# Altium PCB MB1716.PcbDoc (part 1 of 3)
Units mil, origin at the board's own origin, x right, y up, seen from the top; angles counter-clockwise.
Board outline 2806.95 x 1299.21 mil, 4 copper layers (Top Layer, M1, M2, Bottom Layer), stack 62.205 mil thick; 53 components, 45 nets, 298 pads, 399 vias.
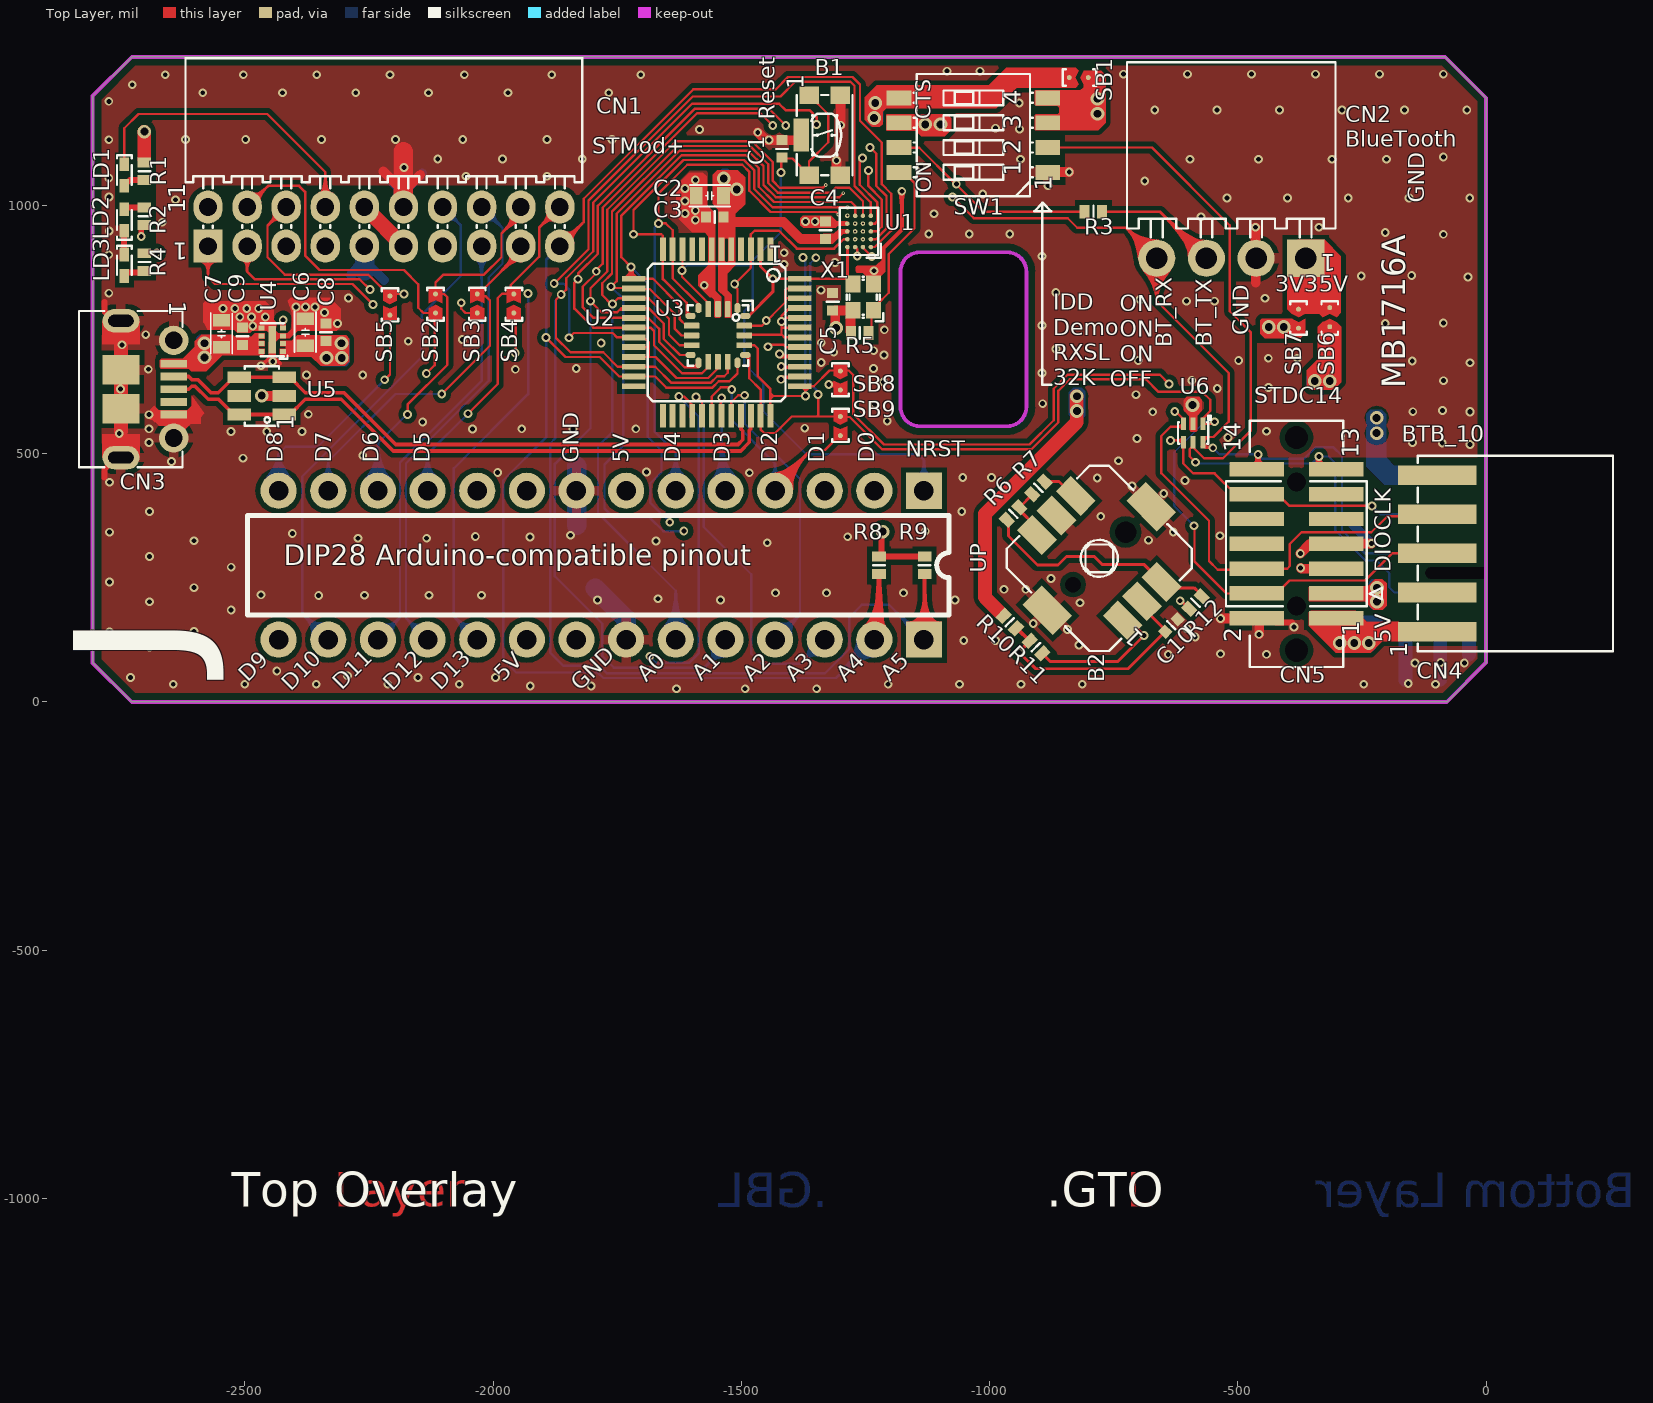
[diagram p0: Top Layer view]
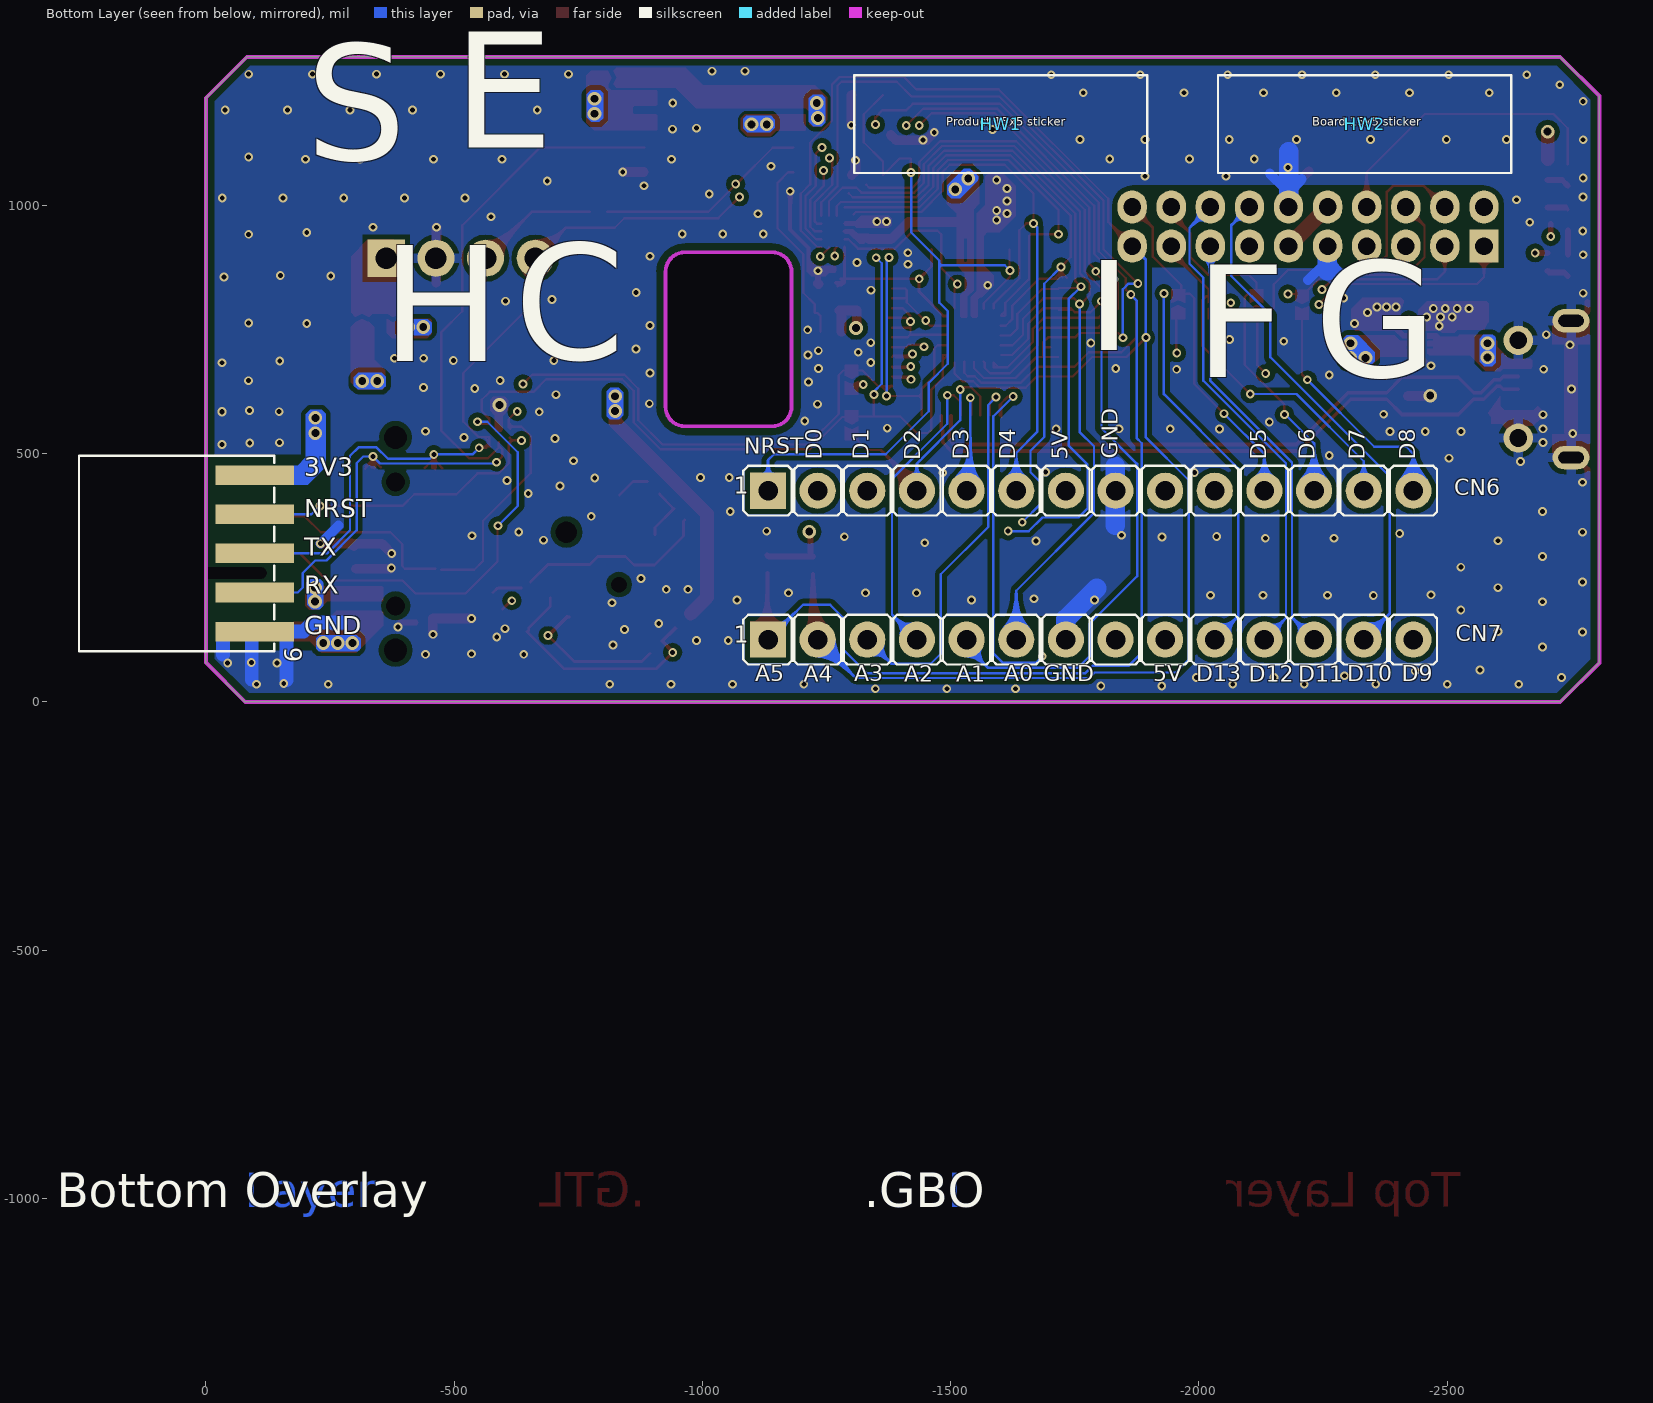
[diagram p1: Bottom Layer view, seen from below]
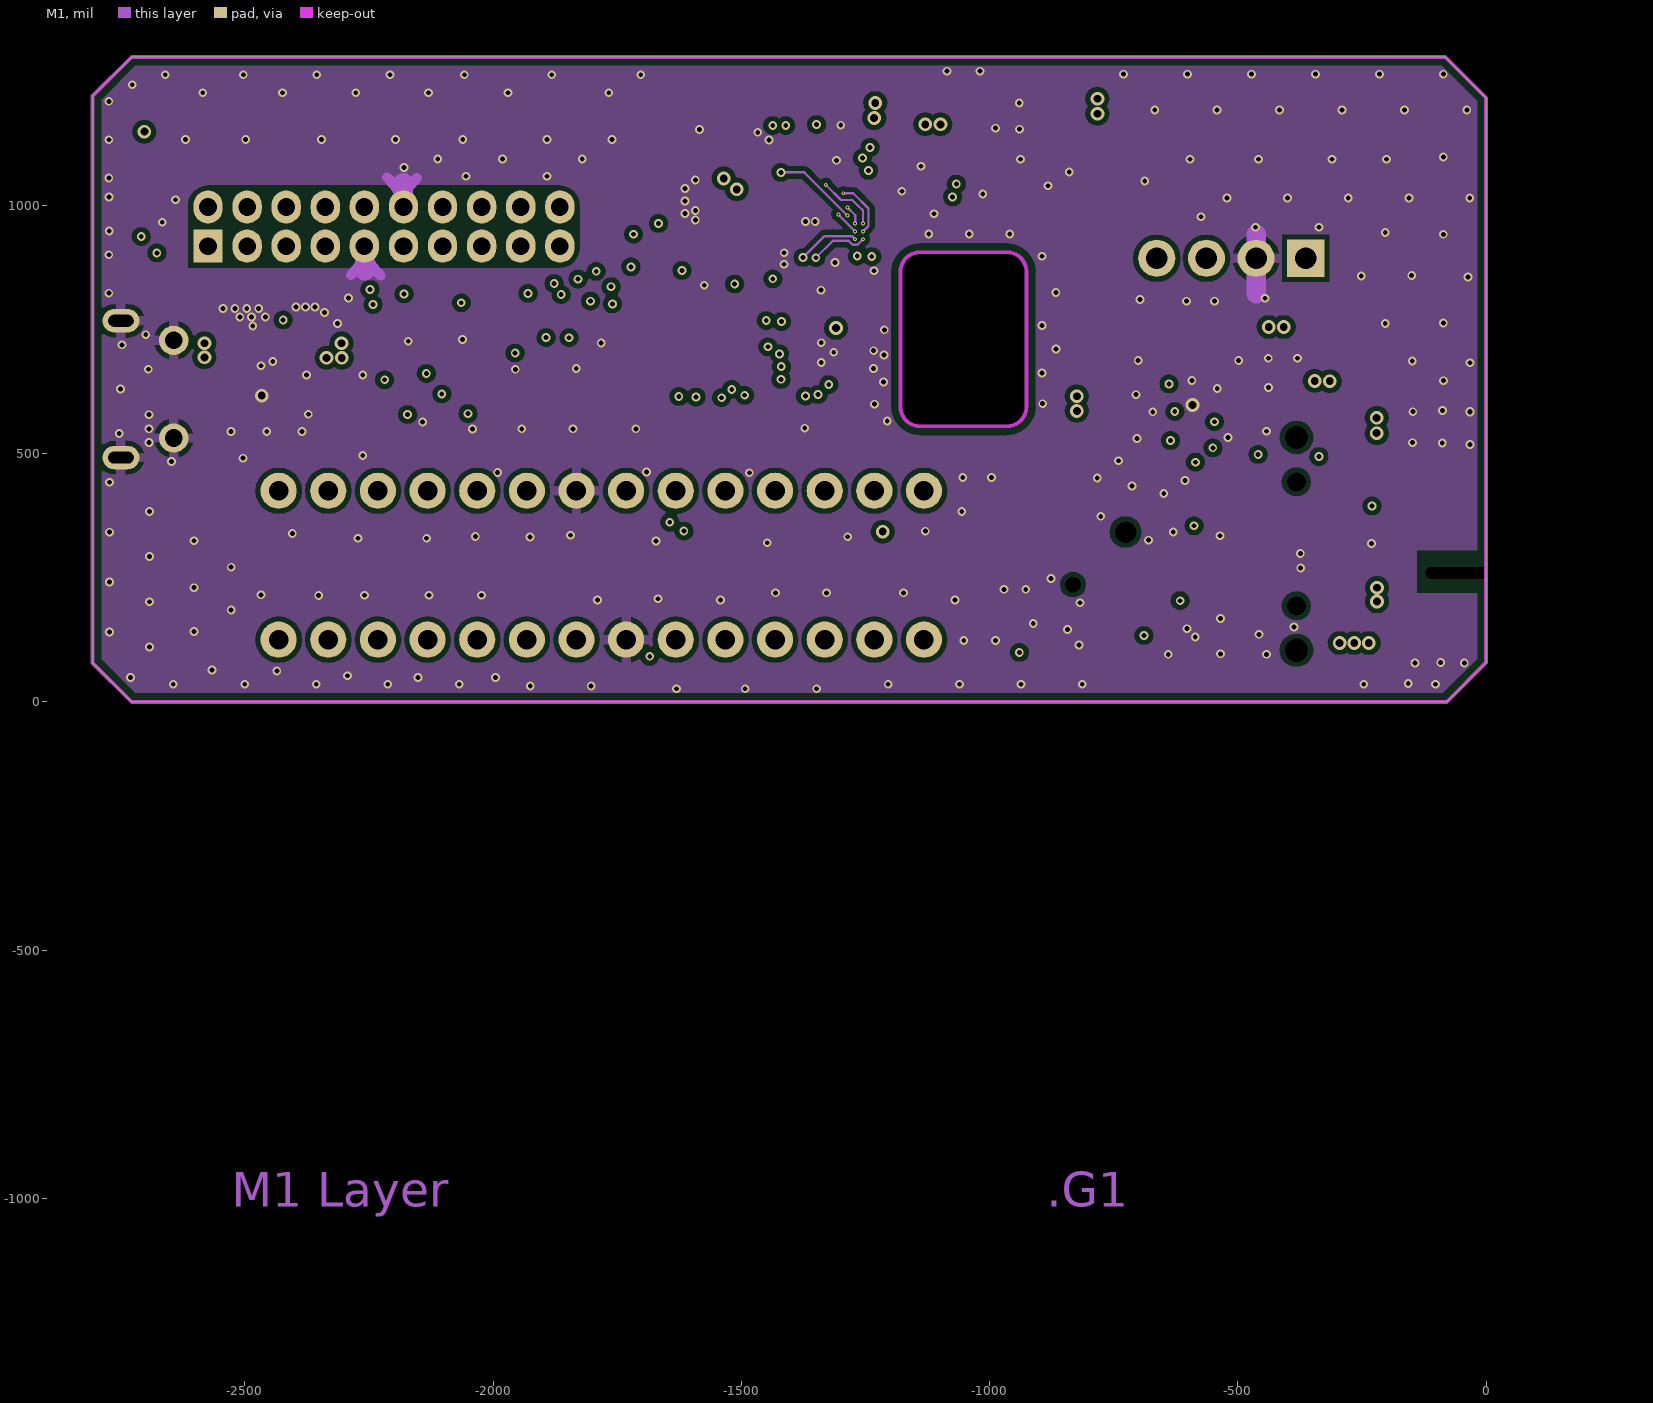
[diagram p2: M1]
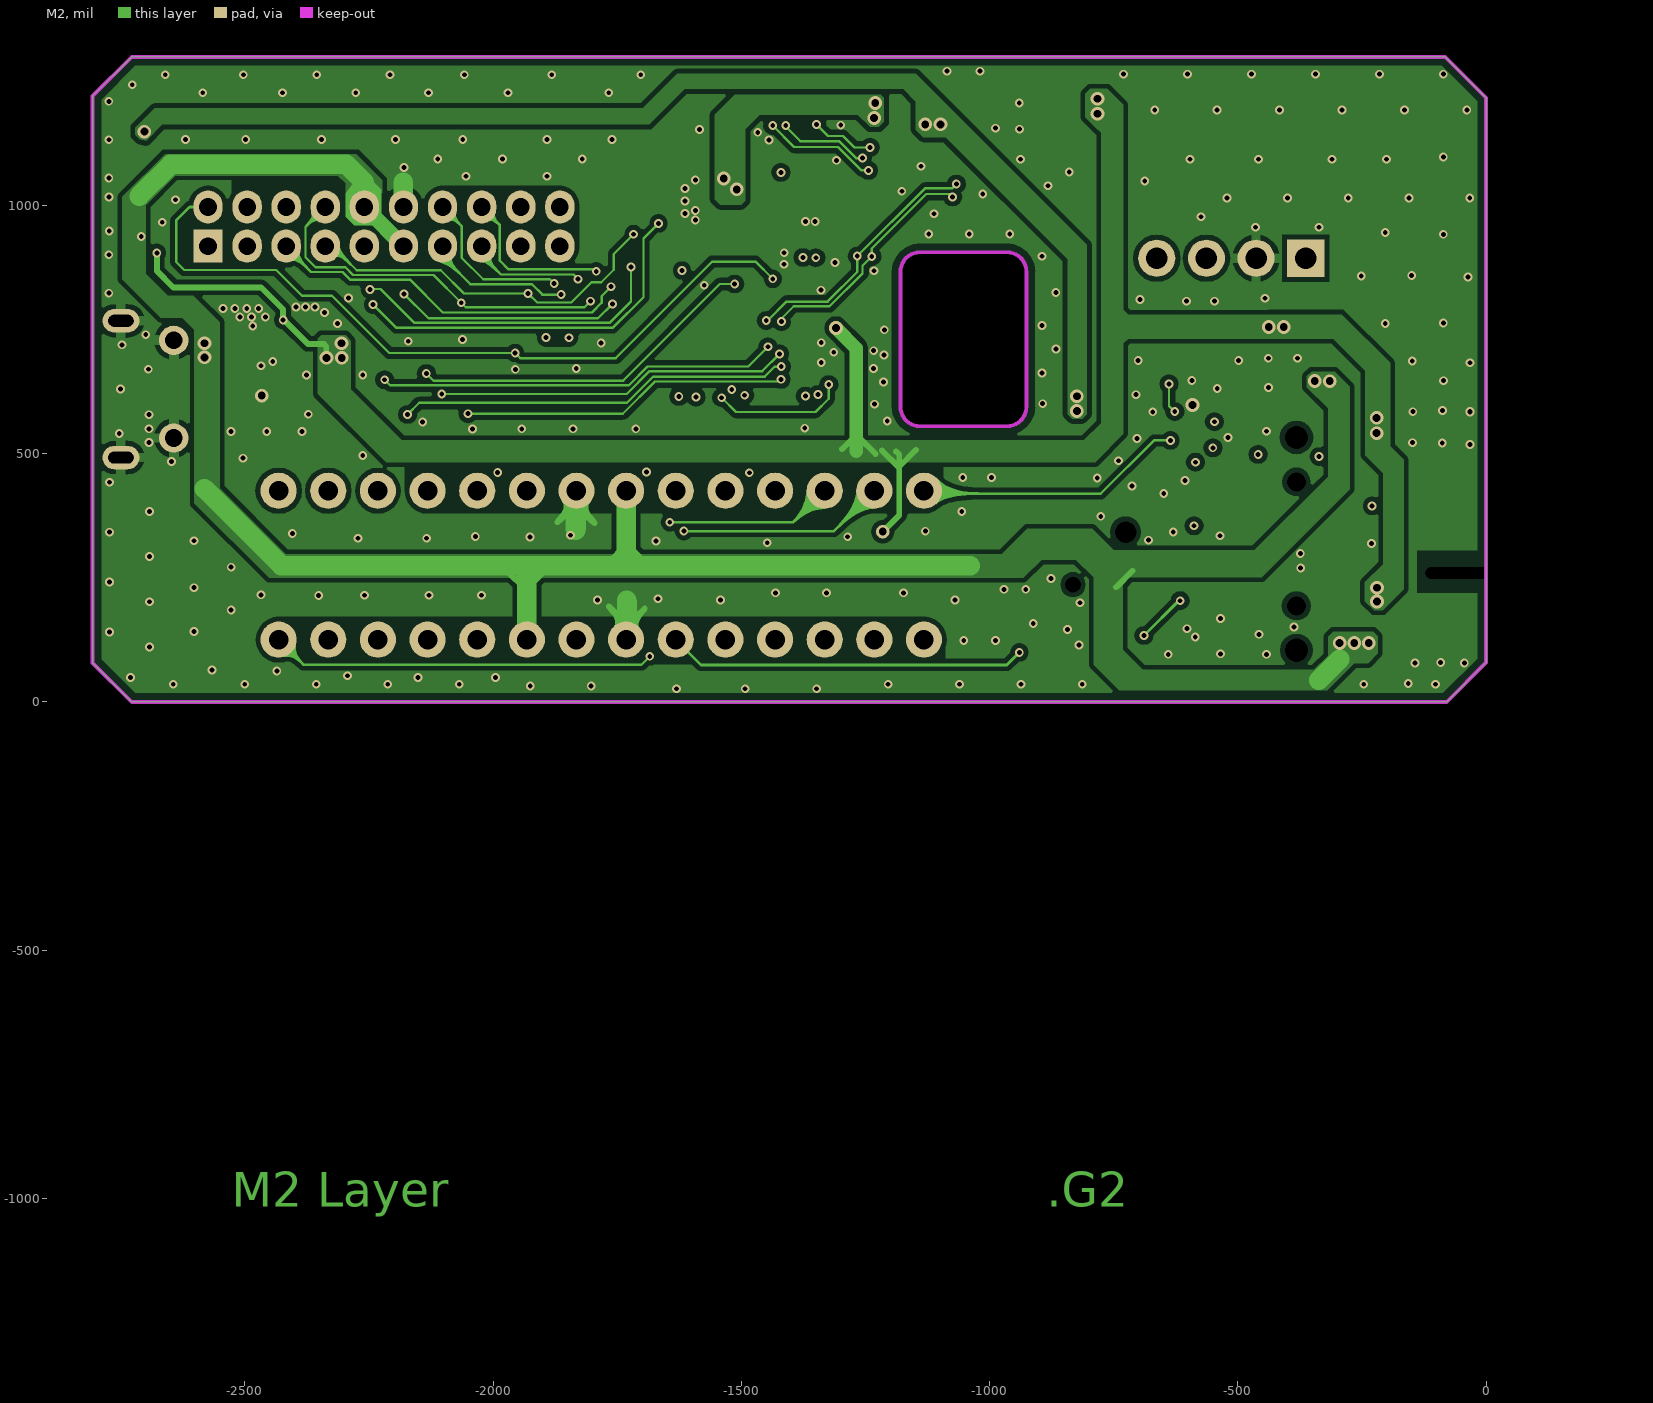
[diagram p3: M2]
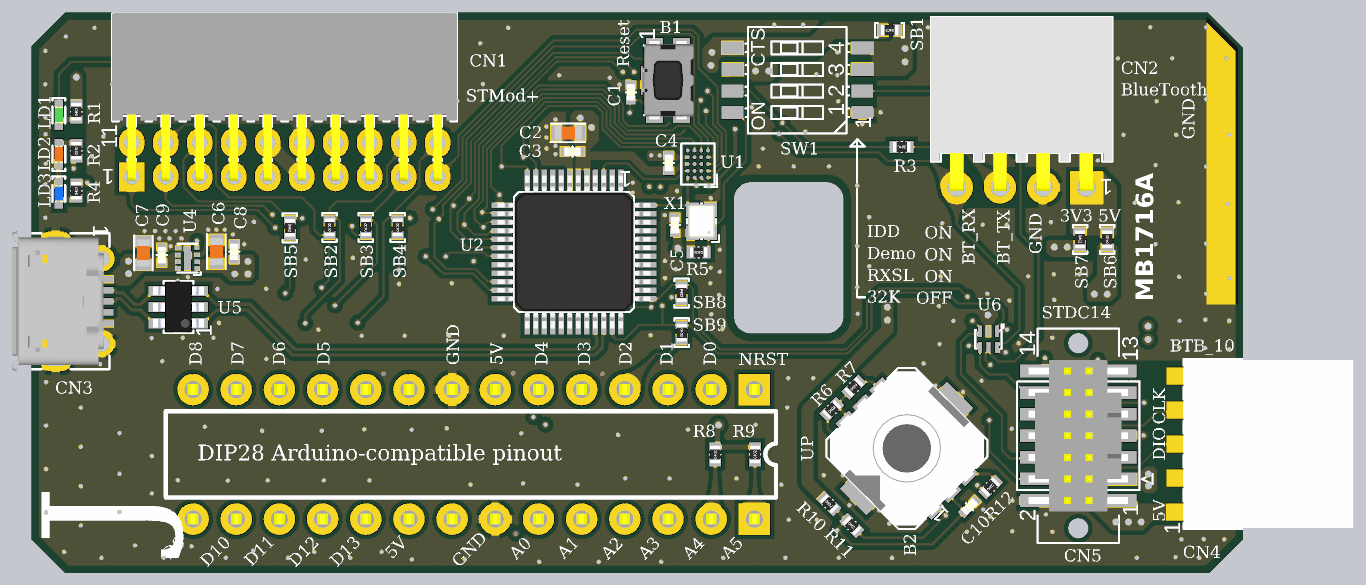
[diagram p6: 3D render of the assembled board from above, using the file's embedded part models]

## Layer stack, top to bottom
Top Solder: solder mask 0.5906, Solder Resist, Dk 3.5
Top Layer: signal copper 1.378
Dielectric 1: core 8.6614, FR-4, Dk 4.2
M1: signal copper 1.378
Dielectric 3: prepreg 39.3701, Dk 4.2
M2: signal copper 1.378
Dielectric 2: core 8.6614, Dk 4.2
Bottom Layer: signal copper 1.378
Bottom Solder: solder mask 0.5906, Solder Resist, Dk 3.5

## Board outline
-2728.21,0 -2806.95,78.74 -2806.95,1220.47 -2728.21,1299.21 -82.13,1299.21 0,1217.08 0,79.21 -79.21,0
cut-out: -1179.6,594.68 ccw(c-1140.23,594.68) -1140.23,555.32 -965.04,555.32 ccw(c-965.04,594.68) -925.67,594.68 -925.67,866.34 ccw(c-965.04,866.34) -965.04,905.71 -1140.23,905.71 ccw(c-1140.23,866.34) -1179.6,866.34

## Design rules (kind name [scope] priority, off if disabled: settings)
BoardOutlineClearance [OnLayer('Top Layer') or OnLayer('Bottom Layer') or OnLayer('Inner 1') or OnLayer('Inner 2')] p1: gap=15.75 ignorepadtopadclearanceinfootprint=FALSE except(7.87: SMDPad-OutlineEdge SMDPad-CavityEdge SMDPad-CutoutEdge SMDPad-SplitBarrior SMDPad-SplitContinuation; 10.63: Poly-OutlineEdge Poly-CavityEdge Poly-CutoutEdge Poly-SplitBarrior Poly-SplitContinuation)
Clearance Clearance_3 [ISVIA vs ISVIA] p1: gap=7.87 ignorepadtopadclearanceinfootprint=FALSE except(0: Arc-Hole Track-Hole SMDPad-Hole THPad-Hole Via-Hole Fill-Hole Poly-Hole Region-Hole Text-Hole)
Clearance Clearance_2 [INPOLYGON vs OnLayer('Keep-Out Layer')] p2: gap=13.78 ignorepadtopadclearanceinfootprint=FALSE except(0: Arc-Hole Track-Hole SMDPad-Hole THPad-Hole Via-Hole Fill-Hole Poly-Hole Region-Hole Text-Hole)
Clearance Clearance_1 [INPOLYGON] p3: gap=9.84 ignorepadtopadclearanceinfootprint=FALSE except(0: Arc-Hole Track-Hole SMDPad-Hole THPad-Hole Via-Hole Fill-Hole Poly-Hole Region-Hole Text-Hole)
Clearance [All] p4: gap=4.72 ignorepadtopadclearanceinfootprint=FALSE except(0: Arc-Hole Track-Hole SMDPad-Hole THPad-Hole Via-Hole Fill-Hole Poly-Hole Region-Hole Text-Hole)
ComponentClearance [All] p1: gap=7.87 collisioncheckmode=3 verticalgap=7.87 showdistances=FALSE
DiffPairsRouting [All] p1: maxlimit=5.91 minlimit=5.91 mostfreqgap=5.91 toplayer_minwidth=7.28 toplayer_maxwidth=7.28 toplayer_prefwidth=7.28 midlayer1_minwidth=7.28 midlayer1_maxwidth=7.28 midlayer1_prefwidth=7.28 midlayer2_minwidth=7.28 midlayer2_maxwidth=7.28 midlayer2_prefwidth=7.28 bottomlayer_minwidth=7.28 bottomlayer_maxwidth=7.28 bottomlayer_prefwidth=7.28 maxuncoupledlength=984.25
HoleSize [All] p1: absolutevalues=TRUE maxlimit=2362.2 minlimit=1 maxpercent=80.000 minpercent=20.000
HoleToHoleClearance [All] p1: gap=0 allowstackedmicrovias=TRUE
MinimumSolderMaskSliver [All] p1: minsoldermaskwidth=0
PlaneConnect [All] p1: planeconnectstyle=Relief reliefexpansion=20 reliefentries=4 reliefconductorwidth=8.27 reliefairgap=8.27
PolygonConnect PolygonConnect_3 [HasFootprint('C0402')    OR HasFootprint('C0603')  OR   HasFootprint('CRY_ECS-327MVATX-1_2X1P6_4P')] p1: connectstyle=Direct reliefconductorwidth=10 reliefentries=4 polygonreliefangle="90 Angle" airgapwidth=10
PolygonConnect PolygonConnect_1 [isvia] p2: connectstyle=Direct reliefconductorwidth=10 reliefentries=4 polygonreliefangle="90 Angle" airgapwidth=10
PolygonConnect [All] p3: connectstyle=Relief reliefconductorwidth=19.68 reliefentries=4 polygonreliefangle="90 Angle" airgapwidth=9.84
RoutingVias RoutingVias_M1 [InDrillLayerPair('Top Layer - M1')] p1: holewidth=3.94 width=7.87 viastyle="Through Hole" minholewidth=3.94 minwidth=7.87 maxholewidth=3.94 maxwidth=7.87
RoutingVias [All] p2: holewidth=11.81 width=19.68 viastyle="Through Hole" minholewidth=9.84 minwidth=17.72 maxholewidth=15.75 maxwidth=27.56
SilkToSilkClearance [All] p1: silktosilkclearance=0
SilkToSolderMaskClearance [IsPad] p1: minsilkscreentomaskgap=0 clearancetoexposedcopper=TRUE
SolderMaskExpansion SolderMaskExpansion_via [IsVia] p1: expansion=1.97 istentingtop=FALSE soldermaskfromhole=TRUE
SolderMaskExpansion [All] p2: expansion=4 istentingtop=FALSE
Width [All] p1: maxlimit=39.37 minlimit=4.72 preferedwidth=5.91
22 further rules are at their usual default settings.

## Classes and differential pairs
net class PB[12..0]: PB0 PB1 PB2 PB4 PB5 PB6 PB8 PB9 PB10 PB11 PB12
net class PA[15..0]: PA0 PA1 PA2 PA3 PA4 PA5 PA6 PA7 PA8 PA9 PA10 PA11 PA12 PA13 PA14
component class "U_STMOD Connectors": CN1
component class "Arduino Connectors": C6 C7 C8 C9 CN2 CN3 CN4 CN5 CN6 CN7 R3 R8 R9 SB2 SB3 SB4 SB5 SB6 SB7 SB8 SB9 U4 U5 U6
net class PC[15..0]: PC0 PC1 PC2 PC3 PC4 PC5 PC6 PC7 PC8 PC9 PC10 PC11 PC12 PC13 PC14 PC15
net class PD[3..0]: PD0 PD1 PD2 PD3
component class U_HW_Mechanical_Parts: HW1 HW2 HW4
component class U_STM32_microcontroller: B1 B2 C1 C2 C3 C4 C5 C10 LD1 LD2 LD3 R1 R2 R4 R5 R6 R7 R10 R11 R12 SB1 SW1 U1 U2 U3 X1
differential pair USBD: +USBD_P -USBD_N

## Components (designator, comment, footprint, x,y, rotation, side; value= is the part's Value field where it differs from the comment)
B1 "SW-PUSH-CMS_KMR2_BLACK" SWI_C&K_Y78B23110FP__ITT_KMR231GLFS -1332.24,1141.73 r90 top locked value=KMR231GLFS
B2 "Joystick MT-008A_M" SWI_XIEJIA_MT-008A_6P -779.05,289.15 r135 top locked value=MT-008A
C1 "Capacitor" C0402 -1418.23,1113.9 r270 top value=100nF (schematic designator C11)
C2 "Capacitor" C0603 -1563.62,1019.92 r0 top value=2.2uF (schematic designator C8)
C3 "Capacitor" C0402 -1553.46,976.61 r0 top value=100nF (schematic designator C7)
C4 "Capacitor" C0402 -1330.32,950.32 r270 top value=100nF (schematic designator C9)
C5 "Capacitor" C0402 -1316.06,806.22 r270 top value=100nF (schematic designator C13)
C6 "Capacitor" C0603 -2378.23,744.65 r270 top value=2.2uF (schematic designator C3)
C7 "Capacitor" C0603 -2547.28,741.65 r270 top value=10uF (schematic designator C1)
C8 "Capacitor" C0402 -2336.85,744.65 r270 top value=100nF (schematic designator C4)
C9 "Capacitor" C0402 -2504.88,736.65 r270 top value=100nF (schematic designator C2)
C10 "Capacitor" C0402 -633.81,154.06 r225 top value=10nF (schematic designator C5)
CN1 "Socket 10X2 STMod+" CON_SAMTEC_SQT-110-01-F-D-RA__STMOD+ -2220.14,957.48 r180 top locked (schematic designator CN6)
CN2 "Socket 4x1" CON_SAMTEC_SSW-104-02-G-S-RA -513.25,893.7 r180 top locked (schematic designator CN4)
CN3 "USB_uB_105017.0001" CON_USBMICROB_MOLEX_105017-0001_H2P90 -2806.95,629.92 r270 top locked value=USB_uB_105017-0001
CN4 "BTB010_061R" CON_AVX_009159010061911_BTB 0,299.13 r270 top locked value=009159010061911 (schematic designator CN7)
CN5 "Header 7x2" CON_STDC14_Receiver_MEDIUM_WITH_STDC14_3D -381.95,318.38 r90 top locked value=STDC14
CN6 "Header 14x1" CON_SAMTEC_TSW-114-07-X-S -1782.24,425.39 r180 bottom locked (schematic designator CN1)
CN7 "Header 14x1" CON_SAMTEC_TSW-114-07-X-S -1782.24,125.39 r180 bottom locked (schematic designator CN2)
HW1 "STICKER_PRODUCT" STICKER_PRODUCT_15X5 -1600.94,1163.78 r180 bottom value="Sticker product"
HW2 "STICKER_BOARD" STICKER_Board_15X5 -2333.82,1163.78 r180 bottom value="Sticker board"
LD1 "LED_green" LED_0402_KINGBRIGHT_KPHHS-1005CGCK_GREEN_1A2K_H0P5 -2743.15,1061.46 r90 top value=GREEN
LD2 "LED_red" LED_0402_KINGBRIGHT_KPHHS-1005SURCK_HYPER-RED_1A2K_H0P5 -2743.15,970.57 r270 top value=RED (schematic designator LD3)
LD3 "LED_blue" LED_0402_KINGBRIGHT_KPHHS-1005QBC-D-V_BLUE_1A2K_H0P5 -2743.15,879.69 r90 top value=BLUE (schematic designator LD2)
R1 "Resistor" R0402 -2702.75,1068.94 r90 top value=680R (schematic designator R12)
R2 "Resistor" R0402 -2702.75,978.54 r270 top value=680R (schematic designator R34)
R3 "Resistor" R0402 -790.87,987.44 r0 top value=330R
R4 "Resistor" R0402 -2702.75,886.02 r90 top value=680R (schematic designator R33)
R5 "Resistor" R0402 -1261.42,743.07 r180 top value=10K (schematic designator R4)
R6 "Resistor" R0402 -952.51,379.29 r45 top value=1K8
R7 "Resistor" R0402 -901.59,431.29 r45 top value=5K1 (schematic designator R5)
R8 "Resistor" R0402 -1222.79,275.04 r90 top value=10K (schematic designator R2)
R9 "Resistor" R0402 -1130.78,275.04 r90 top value=10K (schematic designator R1)
R10 "Resistor" R0402 -959.37,160.76 r315 top value=2K (schematic designator R9)
R11 "Resistor" R0402 -906.59,110.23 r315 top value=510R (schematic designator R8)
R12 "Resistor" R0402 -585.26,199.85 r45 top value=820R (schematic designator R7)
SB1 "SB_ON" SOLDER-BRIDGE_R0402-0R -818.86,1257.64 r180 top (schematic designator SB9)
SB2 "SB_ON" SOLDER-BRIDGE_R0402-0R -2116.22,801.1 r90 top (schematic designator SB4)
SB3 "SB_ON" SOLDER-BRIDGE_R0402-0R -2032.09,801.1 r90 top (schematic designator SB5)
SB4 "SB_ON" SOLDER-BRIDGE_R0402-0R -1958.5,801.1 r90 top (schematic designator SB3)
SB5 "SB_ON" SOLDER-BRIDGE_R0402-0R -2208.03,799.84 r270 top (schematic designator SB6)
SB6 "SB_ON" SOLDER-BRIDGE_R0402-0R -314.84,773.39 r90 top (schematic designator SB7)
SB7 "SB_ON" SOLDER-BRIDGE_R0402-0R -377.76,773.39 r270 top (schematic designator SB8)
SB8 "SB_ON" SOLDER-BRIDGE_R0402-0R -1300.63,648.86 r270 top (schematic designator SB2)
SB9 "SB_ON" SOLDER-BRIDGE_R0402-0R -1300.55,557.13 r270 top (schematic designator SB1)
SW1 "SWITCH_4WAY" SWI_CTS_CTS218-4LP -1032.75,1141.73 r90 top locked value=CT218-4LPSTRI
U1 "STM32G051F8Y6" ICC_WLCSP20_1P94X2P40_P040 -1262.97,947.74 r180 top locked (schematic designator U4)
U2 "STM32C031C6T6" ICC_LQFP48_7X7_P050 -1549.92,744.09 r180 top locked (schematic designator U3)
U3 "STM32C011F6U6" ICC_UFQFPN20_3X3_P050 -1547.24,738.19 r270 top locked (schematic designator U2)
U4 "LD56100" ESD_DFN8-EPAD_1P6X1P2_P040_H0P45 -2445,729.61 r90 top locked value=LD56100DPU33R (schematic designator U1)
U5 "USBLC6-2SC6" ESD_SOT23-6L -2466.06,616.34 r90 top (schematic designator U6)
U6 "ESDALC6V1-5M6" ESD_UQFN-6L_1P45X1_P050 -590.11,541.77 r180 top locked (schematic designator U5)
X1 "ECS-327MVATX" CRY_ECS-327MVATX-1_2X1P6_4P -1254.61,815.16 r90 top value=ECS-327MVATX-1-CN-TR

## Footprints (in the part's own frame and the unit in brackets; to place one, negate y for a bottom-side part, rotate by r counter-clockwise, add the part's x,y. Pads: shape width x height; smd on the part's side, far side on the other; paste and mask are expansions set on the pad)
C0402 [mm]
  rect 0.51x0.56 smd mask+0.05: 1(-0.45,0) 2(0.45,0)
  silkscreen extent 0,-0.3 0,0.3, body extent -0.5,-0.3 0.5,0.3, height 0.4
C0603 [mm]
  rect 0.64x0.89 smd mask+0.05: 1(-0.7,0) 2(0.7,0)
  silkscreen extent -1.05,-0.55 1.02,0.55, body extent -0.9,-0.5 0.9,0.5, height 1.4
CON_AVX_009159010061911_BTB [mm] "MCD-02332"
  round 0 hole 3.4 slot 0.6 at 0 deg unplated mask+0.05: 0(1,-1.4)
  rect 1x4 smd paste-2 mask+0.05: 1(4,-2.5) 2(2,-2.5) 3(0,-2.5) 4(-2,-2.5) 5(-4,-2.5)
  rect 1x4 smd far side paste-2 mask+0.05: 6(4,-2.5) 7(2,-2.5) 8(0,-2.5) 9(-2,-2.5) 10(-4,-2.5)
  silkscreen extent -5,-3.5 5,6.5, body extent -4.95,-3.5 4.95,6.5, height 1.7
CON_SAMTEC_SQT-110-01-F-D-RA__STMOD+ [mm] "SQT-110-01-F-D-RA (connecteur SAMTEC pour interface STMod+ femelle cot?Host) Pinning adapt?non conforme SAMTEC."
  rect 1.5x1.7 hole 0.9 mask+0.05: 1(9,1)
  oval 1.5x1.7 hole 0.9 mask+0.05: 2(7,1) 3(5,1) 4(3,1) 5(1,1) 6(-1,1) 7(-3,1) 8(-5,1) 9(-7,1) 10(-9,1) 11(9,-1) 12(7,-1) 13(5,-1) 14(3,-1) 15(1,-1) 16(-1,-1) 17(-3,-1) 18(-5,-1) 19(-7,-1) 20(-9,-1)
  silkscreen extent -10.15,-8.62 10.15,0.07, body extent -10.15,-8.65 10.15,1.22, height 4
CON_SAMTEC_SSW-104-02-G-S-RA [mm] "MCD-02305"
  rect 1.9x1.9 hole 1.1 mask+0.05: 1(-3.81,0)
  round 1.9 hole 1.1 mask+0.05: 2(-1.27,0) 3(1.27,0) 4(3.81,0)
  silkscreen extent -5.34,-10.03 5.34,-1.07, body extent -5.33,-10.03 5.33,0.2, height 2.41
CON_SAMTEC_TSW-114-07-X-S [mm] "MCD-02306"
  rect 1.85x1.85 / inner round 1.85 / far side rect 1.85x1.85 hole 1 mask+0.05: 1(-16.51,0)
  round 1.85 hole 1 mask+0.05: 2(-13.97,0) 3(-11.43,0) 4(-8.89,0) 5(-6.35,0) 6(-3.81,0) 7(-1.27,0) 8(1.27,0) 9(3.81,0) 10(6.35,0) 11(8.89,0) 12(11.43,0) 13(13.97,0) 14(16.51,0)
  silkscreen extent -17.78,-1.27 17.72,1.27, body extent -17.91,-1.27 17.78,1.27, height 8.38
CON_STDC14_Receiver_MEDIUM_WITH_STDC14_3D [mm] "compatible with FTSH-107-01-L-DV,-K,-A,-P,-ES"
  round 0 hole 1.19 unplated mask+0.05: 0(-5.445,0) 0(5.445,0)
  round 0 hole 0.97 unplated mask+0.05: 0(-3.175,0) 0(3.175,0)
  rect 0.74x2.79 smd mask+0.05: 1(-3.81,-2.032) 2(-3.81,2.032) 3(-2.54,-2.032) 4(-2.54,2.032) 5(-1.27,-2.032) 6(-1.27,2.032) 7(0,-2.032) 8(0,2.032) 9(1.27,-2.032) 10(1.27,2.032) 11(2.54,-2.032) 12(2.54,2.032) 13(3.81,-2.032) 14(3.81,2.032)
  silkscreen extent -6.3,-4.38 6.3,3.6, body extent -6.3,-2.92 6.3,2.92, height 6.6
CON_USBMICROB_MOLEX_105017-0001_H2P90 [mm]
  rect 0.4x1.35 smd mask+0.05: 1(-1.3,4.15) 2(-0.65,4.15) 3(0,4.15) 4(0.65,4.15) 5(1.3,4.15)
  round 1.5 hole 0.9 mask+0.05: 6(-2.5,4.15) 7(2.5,4.15)
  oval 1.2x1.9 hole 0.6 slot 1.3 at 90 deg mask+0.05: 8(3.5,1.45) 9(-3.5,1.45)
  rect 1.5x1.9 smd mask+0.05: 10(-1,1.45) 11(1,1.45)
  Top Layer region: 2.3,2.4 3.5,2.4 3.5,0.5 2.3,0.5 2.3,2.4
  Top Layer region: -3.5,2.4 -2.3,2.4 -2.3,0.5 -3.5,0.5 -3.5,2.4
  silkscreen extent -4,-0.7 4,4.6, body extent -4.1,-1.15 4.1,4.66, height 2.9
CRY_ECS-327MVATX-1_2X1P6_4P [mm] "MCD-02331"
  rect 0.85x0.75 smd mask+0.05: 1(-0.675,-0.525) 2(0.675,-0.525) 3(0.675,0.525) 4(-0.675,0.525)
  silkscreen extent -1.23,-1.02 1.05,0.85, body extent -1.05,-0.85 1.05,0.85, height 0.91
ESD_DFN8-EPAD_1P6X1P2_P040_H0P45 [mm] "MCD-02304"
  rect 0.26x0.3 smd mask+0.035: 1(-0.6,-0.55) 2(-0.2,-0.55) 3(0.2,-0.55) 4(0.6,-0.55) 5(0.6,0.55) 6(0.2,0.55) 7(-0.2,0.55) 8(-0.6,0.55)
  rect 1.4x0.4 smd mask+0.05: 9(0,0)
  silkscreen extent -0.97,-0.77 0.85,0.6, body extent -0.8,-0.65 0.8,0.65, height 0.51
ESD_SOT23-6L [mm]
  rect 0.6x1.2 smd mask+0.05: 1(-0.95,-1.15) 2(0,-1.15) 3(0.95,-1.15) 4(0.95,1.15) 5(0,1.15) 6(-0.95,1.15)
  silkscreen extent -1.53,-0.87 1.53,0.87, body extent -1.52,-1.5 1.52,1.5, height 1.45
ESD_UQFN-6L_1P45X1_P050 [mm]
  rect 0.25x0.65 smd mask+0.05: 1(-0.5,-0.475) 2(0,-0.475) 3(0.5,-0.475) 4(0.5,0.475) 5(0,0.475) 6(-0.5,0.475)
  silkscreen extent -0.9,-0.87 0.77,0.55, body extent -0.77,-0.55 0.77,0.55, height 0.66
ICC_LQFP48_7X7_P050 [mm]
  rect 0.3x1.2 smd mask+0.05: 1(-2.75,-4.25) 2(-2.25,-4.25) 3(-1.75,-4.25) 4(-1.25,-4.25) 5(-0.75,-4.25) 6(-0.25,-4.25) 7(0.25,-4.25) 8(0.75,-4.25) 9(1.25,-4.25) 10(1.75,-4.25) 11(2.25,-4.25) 12(2.75,-4.25) 25(2.75,4.25) 26(2.25,4.25) 27(1.75,4.25) 28(1.25,4.25) 29(0.75,4.25) 30(0.25,4.25) 31(-0.25,4.25) 32(-0.75,4.25) 33(-1.25,4.25) 34(-1.75,4.25) 35(-2.25,4.25) 36(-2.75,4.25)
  rect 1.2x0.3 smd mask+0.05: 13(4.25,-2.75) 14(4.25,-2.25) 15(4.25,-1.75) 16(4.25,-1.25) 17(4.25,-0.75) 18(4.25,-0.25) 19(4.25,0.25) 20(4.25,0.75) 21(4.25,1.25) 22(4.25,1.75) 23(4.25,2.25) 24(4.25,2.75) 37(-4.25,2.75) 38(-4.25,2.25) 39(-4.25,1.75) 40(-4.25,1.25) 41(-4.25,0.75) 42(-4.25,0.25) 43(-4.25,-0.25) 44(-4.25,-0.75) 45(-4.25,-1.25) 46(-4.25,-1.75) 47(-4.25,-2.25) 48(-4.25,-2.75)
  silkscreen extent -3.52,-3.52 3.52,3.52, body extent -4.5,-4.5 4.5,4.5, height 1.6
ICC_UFQFPN20_3X3_P050 [mm] "MCD-02302"
  oct 0.525x0.3 smd mask+0.05: 1(-1.4,1) 5(-1.4,-1) 11(1.4,-1) 15(1.4,1)
  rrect25% 0.8x0.3 smd mask+0.05: 2(-1.35,0.5) 3(-1.35,0) 4(-1.35,-0.5) 12(1.35,-0.5) 13(1.35,0) 14(1.35,0.5)
  oct 0.3x0.525 smd mask+0.05: 6(-1,-1.4) 10(1,-1.4) 16(1,1.4) 20(-1,1.4)
  rrect25% 0.3x0.8 smd mask+0.05: 7(-0.5,-1.35) 8(0,-1.35) 9(0.5,-1.35) 17(0.5,1.35) 18(0,1.35) 19(-0.5,1.35)
  silkscreen extent -1.78,-1.55 1.54,1.78, body extent -1.5,-1.5 1.5,1.5, height 0.55
ICC_WLCSP20_1P94X2P40_P040 [mm] "MCD-02303"
  round 0.23 smd mask+0.05: A1(-0.6,0.8) A2(-0.2,0.8) A3(0.2,0.8) A4(0.6,0.8) B1(-0.6,0.4) B2(-0.2,0.4) B3(0.2,0.4) B4(0.6,0.4) C1(-0.6,0) C2(-0.2,0) C3(0.2,0) C4(0.6,0) D1(-0.6,-0.4) D2(-0.2,-0.4) D3(0.2,-0.4) D4(0.6,-0.4) E1(-0.6,-0.8) E2(-0.2,-0.8) E3(0.2,-0.8) E4(0.6,-0.8)
  silkscreen extent -1.12,-1.21 0.98,1.35, body extent -0.98,-1.21 0.98,1.21, height 0.6
LED_0402_KINGBRIGHT_KPHHS-1005CGCK_GREEN_1A2K_H0P5 [mm] "MCD-00707"
  rect 0.7x0.5 smd mask+0.05: 1(-0.55,0) 2(0.55,0)
  silkscreen extent -0.5,-0.38 1,0.38, body extent -0.5,-0.3 0.51,0.3, height 0.6
LED_0402_KINGBRIGHT_KPHHS-1005QBC-D-V_BLUE_1A2K_H0P5 [mm] "MCD-00706"
  rect 0.7x0.5 smd mask+0.05: 1(-0.55,0) 2(0.55,0)
  silkscreen extent -0.5,-0.38 1,0.38, body extent -0.5,-0.3 0.51,0.3, height 0.6
LED_0402_KINGBRIGHT_KPHHS-1005SURCK_HYPER-RED_1A2K_H0P5 [mm] "MCD-00708"
  rect 0.7x0.5 smd mask+0.05: 1(-0.55,0) 2(0.55,0)
  silkscreen extent -0.5,-0.38 1,0.38, body extent -0.5,-0.3 0.51,0.3, height 0.6
R0402 [mm]
  rect 0.51x0.7 smd mask+0.05: 1(-0.45,0) 2(0.45,0)
  silkscreen extent 0,-0.3 0,0.3, body extent -0.52,-0.3 0.52,0.3, height 0.4
SOLDER-BRIDGE_R0402-0R [mil] "MCD-01619"
  round 10 smd paste-393.7: 1(-17.72,0) 2(20.67,0)
  Top Layer region: -30.51,-13.78 -30.51,13.78 -8.37,13.78 -1.48,0 -8.37,-13.78
  Top Layer region: 1.48,13.78 8.37,0 1.48,-13.78 30.51,-13.78 30.51,13.78
  silkscreen extent -33,-17 33,17, body extent -20,-12 20,12, height 14
STICKER_Board_15X5 [mil] "Sticker to mention board CPN code"
  silkscreen extent -295,-98 295,98, body extent -295,-98 295,98, height 0
STICKER_PRODUCT_15X5 [mil] "Sticker to mention board CPN code"
  silkscreen extent -295,-98 295,98, body extent -295,-98 295,98, height 0
SWI_C&K_Y78B23110FP__ITT_KMR231GLFS [mm] "MCD-00715"
  rect 0.9x1 smd mask+0.05: 1(2.05,0.8) 2(2.05,-0.8) 3(-2.05,0.8) 4(-2.05,-0.8)
  rect 1.7x0.8 smd mask+0.05: 5(0,1.2)
  silkscreen extent -2.05,-1.43 2.05,1.43, body extent -2.3,-1.5 2.3,1.5, height 2.1
SWI_CTS_CTS218-4LP [mm] "GULL WING TERMINAL"
  rect 0.76x1.27 smd mask+0.05: 1(-1.905,-3.81) 2(-0.635,-3.81) 3(0.635,-3.81) 4(1.905,-3.81) 5(1.905,3.81) 6(0.635,3.81) 7(-0.635,3.81) 8(-1.905,3.81)
  silkscreen extent -3.13,-3.05 3.13,3.05, body extent -3.18,-4.32 3.18,4.32, height 2.85
SWI_XIEJIA_MT-008A_6P [mm] "MCD-00132"
  rect 1.8x1.1 smd mask+0.05: 1(-3.1,1.4) 2(-3.1,0) 3(-3.1,-1.4) 4(3.1,1.4) 5(3.1,0) 6(3.1,-1.4)
  rect 2.2x1.4 smd mask+0.05: 7(0,3.75) 8(0,-3.75)
  round 0 hole 0.8 unplated paste-10 mask+0.05: NPTH1(0,1.9)
  round 0 hole 1.1 unplated paste-10 mask+0.05: NPTH2(0,-1.9)
  silkscreen extent -3.7,-3.7 3.7,3.7, body extent -3.85,-3.75 3.85,3.75, height 5.2

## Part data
B1: library part MCD-01485, "Microminiature Tact Switch for SMT - KMR 2 Series - 1.9 mm height", Manufacturer=C&K, Manufacturer_Part_Number=KMR231GLFS
B2: library part MCD-00132, "Joystick, 4 dir, 1 OK", Manufacturer="XIEJIA ELECTRONICS", Manufacturer_Part_Number=MT-008A
C1 C3 C4 C5 C8 C9: library part MCD-00006, "Capacitor, MLCC, 100nF, 16V, X7R, +/-10%, 0402, T=0.5mm", Alternate_Manufacturer=MURATA, Alternate_Manufacturer_Part_Number=GCM155R71C104KA55D, Manufacturer=YAGEO, Manufacturer_Part_Number=CC0402KRX7R7BB104, Package=C0402
C2 C6: library part MCD-00654, "Capacitor, MLCC, 2.2uF, 16V, X5R,+/-10%, 0603, T=0.8mm", Alternate_Manufacturer=MURATA, Alternate_Manufacturer_Part_Number=GCM155R71C104KA55D, Manufacturer=YAGEO, Manufacturer_Part_Number=CC0603KRX5R7BB225, Package=C0603
C7: library part MCD-01124, "Capacitor, MLCC, 10uF, 10V, X5R, +/-10%, 0603, T=0.8mm", Alternate_Manufacturer=MURATA, Alternate_Manufacturer_Part_Number=GCM155R71C104KA55D, Manufacturer_Part_Number=GRM188R61A106KAAL, Package=C0603
C10: library part MCD-00011, "Capacitor, MLCC, 10nF, 16V, X7R, +/-10%, 0402, T=0.5mm", Alternate_Manufacturer=MURATA, Alternate_Manufacturer_Part_Number=GCM155R71C104KA55D, Manufacturer=YAGEO, Manufacturer_Part_Number=CC0402KRX7R7BB103, Package=C0402
CN1: library part MCD-00309, "Socket 10x2, 2.00mm, RA, TH, Height 6.35mm/2.29mm", Alternate_Manufacturer=JIUBABA;CONNECT, Alternate_Manufacturer_Part_Number=FH200020C-12300;CNT-F200-2*10-GD-635/2.3, Manufacturer=SAMTEC, Manufacturer_Part_Number=SQT-110-01-F-D-RA
CN2: library part MCD-02305, "Socket, 4x1, 2.54mm, RA, TH, height 10.67/2.41mm", Alternate_Manufacturer=N/A, Manufacturer=SAMTEC, Manufacturer_Part_Number=SSW-104-02-G-S-RA
CN3: library part MCD-00028, "USB-MICRO-B, 0.65mm, RA, SMT, Bottom Mount,", Manufacturer=MOLEX, Manufacturer_Part_Number=1050170001
CN4: library part MCD-02332, "SSL Connector, 10 Position Adapter, Bridge Board to Board - Card Edge 0.079\" (2.00mm)", Alternate_Manufacturer=N/A, Manufacturer=AVX, Manufacturer_Part_Number=009159010061911
CN5: library part MCD-01241, "Header 7x2, 1.27mm, Dual row, Straight, \"STDC14_MEDIUM\" : footprint compatible with FTSH-107-01-L-DV,-K,-A,-P,-ES (use \"STDC14_BIG\" to also be compatible with SHF-107-01-L-D-SM,-K) and FTSH-105-01-L-DV-K (MIPI10)", Manufacturer=SAMTEC, Manufacturer_Part_Number=FTSH-107-01-L-DV-K
CN6 CN7: library part MCD-02306, "Header, 14x1, 2,54mm, VR, TH, Height 5.84mm/2.54mm", Alternate_Manufacturer=N/A, Manufacturer=SAMTEC, Manufacturer_Part_Number=TSW-114-07-G-S
HW1: library part MCD-02191, "Sticker product 15x5 mm", Alternate_Manufacturer=N/A
HW2: library part MCD-02192, "Sticker board 15x5 mm", Alternate_Manufacturer=N/A
LD1: library part MCD-00707, "LED 0402 Green", Alternate_Manufacturer="OSRAM OPTO SEMICONDUCTORS", Alternate_Manufacturer_Part_Number="LG Q396-PS-35", Manufacturer=KINGBRIGHT, Manufacturer_Part_Number=KPHHS-1005CGCK, Package="LED 0402"
LD2: library part MCD-00708, "LED 0402 Red", Alternate_Manufacturer="OSRAM OPTO SEMICONDUCTORS", Alternate_Manufacturer_Part_Number="LS Q976-NR-1", Manufacturer=KINGBRIGHT, Manufacturer_Part_Number=KPHHS-1005SURCK, Package="LED 0402"
LD3: library part MCD-00706, "LED 0402 Blue", Manufacturer=KINGBRIGHT, Manufacturer_Part_Number=KPHHS-1005QBC-D-V, Package="LED 0402"
R1 R2 R4: library part MCD-00507, "Resistor,680R,0402,1%,1/16W", Alternate_Manufacturer=YAGEO, Alternate_Manufacturer_Part_Number=RT0402FRE07100KL, Manufacturer_Part_Number=RC0402FR-07680RL, Package=R0402
R3: library part MCD-00062, "Resistor,330R,0402,1%,1/16W", Alternate_Manufacturer=YAGEO, Alternate_Manufacturer_Part_Number=RT0402FRE07100KL, Manufacturer_Part_Number=RC0402FR-07330RL, Package=R0402
R5 R8 R9: library part MCD-00053, "Resistor,10K,0402,1%,1/16W", Alternate_Manufacturer=YAGEO, Alternate_Manufacturer_Part_Number=RT0402FRE07100KL, Manufacturer_Part_Number=RC0402FR-0710KL, Package=R0402
R6: library part MCD-00409, "Resistor,1K8,0402,1%,1/16W", Alternate_Manufacturer=YAGEO, Alternate_Manufacturer_Part_Number=RT0402FRE07100KL, Manufacturer_Part_Number=RC0402FR-071K8L, Package=R0402
R7: library part MCD-00333, "Resistor,5K1,0402,1%,1/16W", Alternate_Manufacturer=YAGEO, Alternate_Manufacturer_Part_Number=RT0402FRE07100KL, Manufacturer_Part_Number=RC0402FR-075K1L, Package=R0402
R10: library part MCD-00419, "Resistor,2K,0402,1%,1/16W", Alternate_Manufacturer=YAGEO, Alternate_Manufacturer_Part_Number=RT0402FRE07100KL, Manufacturer_Part_Number=RC0402FR-072KL, Package=R0402
R11: library part MCD-00064, "Resistor,510R,0402,1%,1/16W", Alternate_Manufacturer=YAGEO, Alternate_Manufacturer_Part_Number=RT0402FRE07100KL, Manufacturer_Part_Number=RC0402FR-07510RL, Package=R0402
R12: library part MCD-00527, "Resistor,820R,0402,1%,1/16W", Alternate_Manufacturer=YAGEO, Alternate_Manufacturer_Part_Number=RT0402FRE07100KL, Manufacturer_Part_Number=RC0402FR-07820RL, Package=R0402
SB1 SB2 SB3 SB4 SB5 SB6 SB7 SB8 SB9: library part MCD-01618, "Solder Bridge 0402 ON", Manufacturer=YAGEO, Manufacturer_Part_Number=RC0402JR-070RL, Package=SB0402
SW1: library part MCD-00167, "Quad SPST surface mount switch. 1.27mm pitch. Tinned legs.", Manufacturer=CTS, Manufacturer_Part_Number=CT218-4LPSTRI
U1: library part MCD-02303, "MCU, ARM™-based 32-bit MCU Cortex-M0+", Alternate_Manufacturer=N/A, Manufacturer=STMICROELECTRONICS, Package=WLCSP20
U2: library part MCD-02301, "MCU, ARM™-based 32-bit MCU Cortex-M0+, 32KB Flash, 6KB SRAM", Alternate_Manufacturer=N/A, Manufacturer=STMICROELECTRONICS, Package=LQFP48
U3: library part MCD-02313, "MCU, ARM™-based 32-bit MCU Cortex-M0+, 32KB Flash, 6KB SRAM", Alternate_Manufacturer=N/A, Manufacturer=STMICROELECTRONICS, Package=UFQFPN20
U4: library part MCD-02304, "LDO, 1 A very low dropout fast transient ultra-low noise linear regulator", Alternate_Manufacturer=N/A, Manufacturer=STMICROELECTRONICS, Manufacturer_Part_Number=LD56100DPU33R, Package=DFN8
U5: library part MCD-00163, "Very low capacitance ESD protection", Manufacturer=STMICROELECTRONICS, Manufacturer_HQ_COO=EU
U6: library part MCD-01457, "ESD protection , 5 lines", Manufacturer=STMICROELECTRONICS, Manufacturer_HQ_COO=EU, Package=QFN
X1: library part MCD-02331, "Oscillator 32.768KHz, +-25ppm, Vcc: 1.6V ~ 3.3V , Tri-State pin, SMD", Alternate_Manufacturer=N/A, Manufacturer="ECS INC. INTERNATIONAL", Manufacturer_Part_Number=ECS-327MVATX-1-CN-TR, Package=2.0x1.6mm

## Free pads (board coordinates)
  round 20 on Mech16: 1(-2067.11,-1289.78) 1(-143.98,-1289.78)

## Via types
v1: diameter 17.72, hole 9.84, Top Layer to Bottom Layer, tented both sides, 357 vias
v2: diameter 27.56, hole 15.75, Top Layer to Bottom Layer, tented both sides, 31 vias
v3: diameter 7.87, hole 3.94, Top Layer to M1, tented both sides, 11 vias

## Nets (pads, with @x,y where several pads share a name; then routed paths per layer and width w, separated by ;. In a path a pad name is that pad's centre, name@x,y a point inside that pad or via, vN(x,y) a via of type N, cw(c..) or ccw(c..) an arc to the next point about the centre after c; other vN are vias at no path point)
3V3: C5.2 C6.2 C8.2 CN4.10 CN5.3 R4.2 R5.2 R8.2 R9.2 SB1.1 SB7.2 SW1.3 SW1.4 U4.1 U4.2 U4.4 X1.4 | length 1635.5
  Top Layer w11.81: R4.2@-2702.75,903.74 -2702.16,904.33 v1@-2675.39,904.33 ; U4.4@-2423.35,755.04 -2423.35,769.33 v1(-2423.11,769.57) ; v2(-1215.12,342.95) -1215.59,342.95 -1217.87,340.67 -1217.87,297.67 R8.2@-1222.79,292.76 -1133.42,292.76 R9.2@-1130.78,295.39
  Top Layer w19.68: v2(-1309.53,753.15) -1311.18,754.8 -1311.18,788.5 -1275.95,788.5 -1280.04,784.41 R5.2@-1280.04,745.79 ; SW1.3@-882.75,1166.73 SW1.3@-879.84,1163.82
  M2 w11.81: v1(-2677.56,904.33) -2677.56,868.23 -2644.25,834.92 -2467.4,834.92 -2423.11,790.63 v1@-2423.11,770.91 ; v1(-2423.11,769.57) v1@-2423.11,770.91 ; v2@-2336.18,696.77 -2336.18,716.06 -2341.34,721.22 -2373.43,721.22 v1@-2423.11,770.91 ; -1297.05,509.49 -1264.06,542.48 ; -1262.6,532.17 -1229.61,499.17 ; -1217.05,506.38 -1184.06,473.39 ; v2(-1215.12,342.95) -1182.13,375.94 -1182.13,498.23 -1188.35,504.45 ; -1181.57,474.25 -1148.58,507.24
  M2 w27.56: v2(-1309.53,753.15) -1268.5,712.13 -1268.5,505.51
  Bottom Layer w27.56: v2(-220.35,572.13) -220.35,477.83 -199.13,456.61 CN4.10@-98.43,456.61
  other v2: -219.68,202.28 -219.68,229.84 -220.35,541.42 -2335.71,693.03 -2305.04,693.03 -2305.51,722.36 -437.68,755.2 -407.56,755.2 -782.84,1184.59 -782.84,1215.1
5V: C7.2 C9.2 CN1.6 CN1.15 CN3.1 CN4.1 CN5.1 CN6.7 CN7.9 R2.2 SB6.1 U4.6 U4.7 U4.8 | length 3055.3
  Top Layer w11.81: v1(-2709.02,937.4) R2.2@-2709.02,962.99
  Top Layer w19.68: C7.2@-2547.28,714.09 -2544.96,716.42 C9.2@-2504.96,716.42
  Top Layer w31.5: CN1.15@-2259.51,996.85 CN1.6@-2175.52,912.87
  M2 w11.81: -1969.88,261.38 -1936.89,228.39 ; -1927.36,232.76 -1894.37,265.75 ; -1766.69,281.93 -1733.7,314.92 ; -1727.01,314.13 -1694.02,281.14 ; -745.12,231.04 -712.13,264.03
  M2 w31.5: CN1.15@-2259.51,996.85 CN1.6@-2175.52,912.87
  M2 w39.37: -2713.07,1018.98 -2649.33,1082.72 -2295.94,1082.72 -2259.51,1046.28 CN1.15@-2259.51,996.85 ; -2581.73,429.8 -2426.61,274.68 -1938.11,274.68 ; CN7.9@-1932.24,125.39 -1932.24,268.81 -1938.11,274.68 ; CN6.7@-1732.24,425.39 -1732.24,280.36 -1737.91,274.68 ; -1039.12,274.68 -1737.91,274.68 ; -336.89,43.66 -294.88,85.67 ; -1938.11,274.68 -1737.91,274.68
  other v2: -294.88,118.66 -265.63,118.66 -236.38,118.66 -314.84,646.18 -344.84,646.57 -2581.69,693.94 -2581.69,722.52
DEMO_3V3: R1.2 R10.1 SW1.6 | length 584.2
  Top Layer w11.81: R1.2@-2700.04,1089.37 R1.2@-2699.64,1089.76
  Top Layer w27.56: R1.2@-2702.75,1092.87 v2(-2702.75,1148.74) ; R10.1@-976.74,178.14 -1009.12,210.51 -1009.12,378.76 -824.21,563.67 v2(-824.21,586.14) ; v2@-825.12,586.14 v2@-825.12,615.87
  other v2: -824.21,615.87 -1129.65,1163.31 -1099.09,1163.31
